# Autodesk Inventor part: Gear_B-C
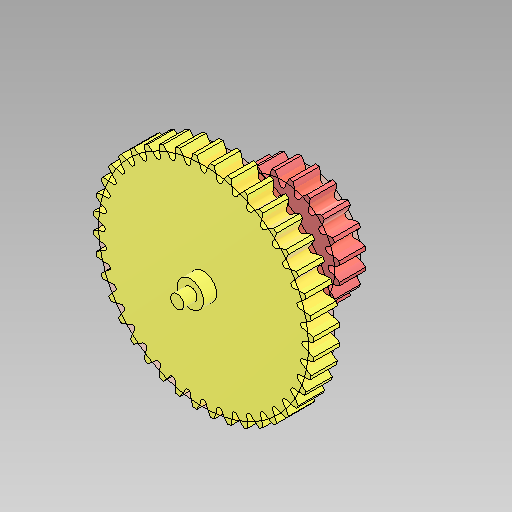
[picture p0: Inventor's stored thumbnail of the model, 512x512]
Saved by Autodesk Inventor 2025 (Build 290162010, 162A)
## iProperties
Created: 2024-10
Part Number: Gear_B-C
Material: Generic
Document SubType Name: Modeling
Designer: Dennis
Mass: 64.8863 g
Surface Area: 207.712 cm^2
Volume: 64.8863 cm^3
Density: 1 g/cm^3
Appearance: Default
Author: Dennis
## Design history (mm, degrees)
derived "Gear_B.ipt"
derived "Gear_C.ipt"
feature "Move Body1"
combine "Combine1"
  node "Solid1_1"
sketch "Sketch1"
  geometry: C1 r 5 at (15.472, -12.135); 1 further point
  constraints: 1 centre point, 1 coincident
  dimensions: "d5" = 10 diameter of C1
extrude "Extrusion1" join sketch "Sketch1" stored distance "d6" = 10; taper "d7" = 0 deg
sketch "Sketch2"
  geometry: C1 r 40 at (34.598, -19.493); 1 further point
  constraints: 1 centre point, 1 coincident
  dimensions: "d8" = 80 diameter of C1
extrude_surface "ExtrusionSrf1" sketch "Sketch2" dims "d9" = 10, "d10" = 0
sketch "Sketch3"
  geometry: C1 r 20 at (-12.776, -16.016); 1 further point
  constraints: 1 centre point, 1 coincident
  dimensions: "d11" = 40 diameter of C1
extrude_surface "ExtrusionSrf2" sketch "Sketch3" dims "d12" = 10, "d13" = 0
feature "Solid1::Gear_B.ipt" dims "d0" = 10
tag "TaggingFeature1"
feature "Solid1::Gear_C.ipt" dims "d1" = 10
tag "TaggingFeature2"
body "Srf1"
body "Srf2"
body "Solid1"
other parameters: "d2" = 0, "d3" = 0
